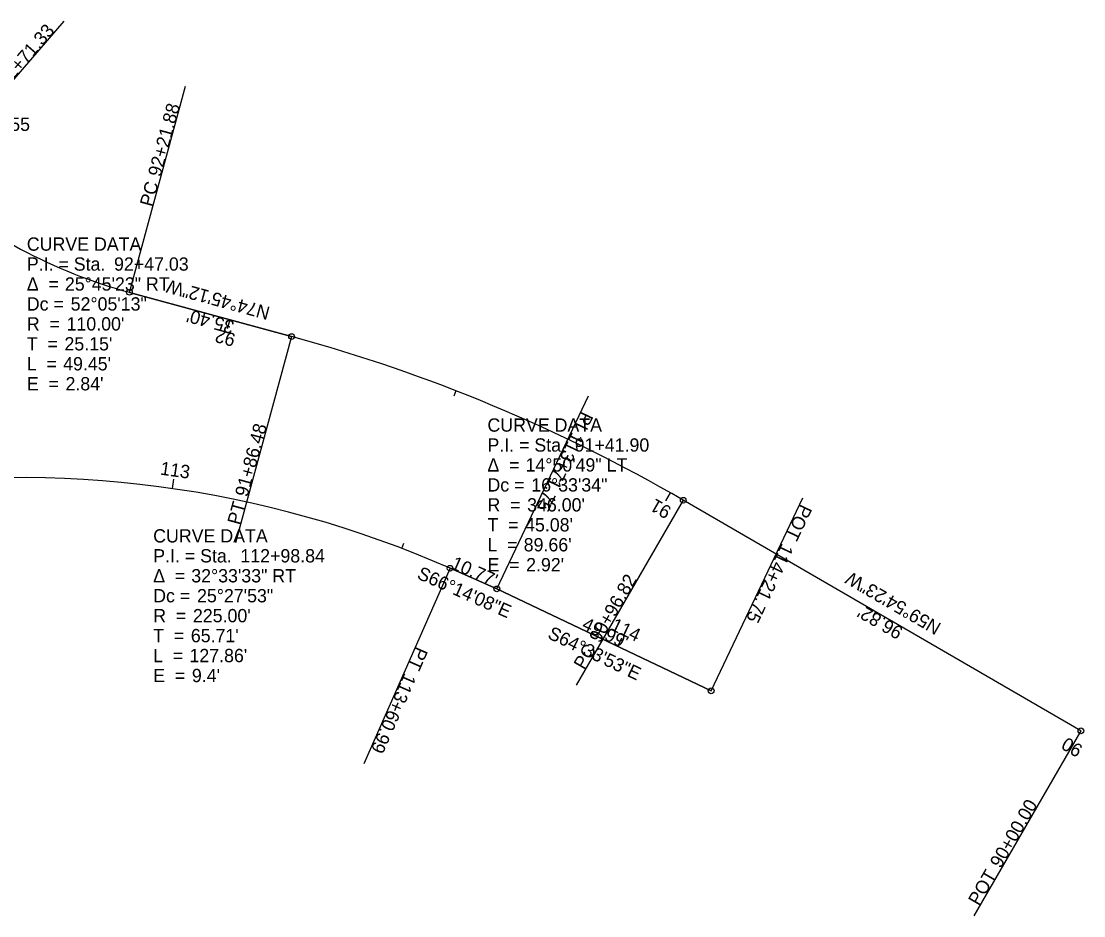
# Model space of a CAD drawing. Extents: x 2047391 to 2047982, y 456752 to 457262.
# Drawn here: x 2047758.1 to 2047982, y 456871 to 457059.3 of the extents above; entities that cross this region are included whole.
import ezdxf

# ---------------------------------------------------------------- set-up
doc = ezdxf.new("R2010")
doc.units = 0
for name, color, linetype in [('GE_P_Alignment', 7, 'Continuous'), ('GE_P_Alignment_100_Bearings', 7, 'Continuous'), ('GE_P_Alignment_100_Cardinal_Points', 7, 'Continuous'), ('GE_P_Alignment_100_Curve_Data', 7, 'Continuous'), ('GE_P_Alignment_100_Distances', 7, 'Continuous'), ('GE_P_Alignment_100_Stations', 7, 'Continuous')]:
    doc.layers.add(name, color=color, linetype=linetype)

msp = doc.modelspace()

# ---------------------------------------------------------------- linework, layer by layer
at = {"layer": 'GE_P_Alignment'}
for p, q in [((2047780.93, 457002.26), (2047815.09, 456992.95)), ((2047815.09, 456992.95), (2047780.93, 457002.26)), ((2047981.35, 456909.94), (2047897.59, 456958.49)), ((2047981.35, 456909.94), (2047897.59, 456958.49)), ((2047981.35, 456909.94), (2047897.59, 456958.49)), ((2047858.32, 456939.83), (2047848.46, 456944.17)), ((2047848.46, 456944.17), (2047858.32, 456939.83)), ((2047903.47, 456918.36), (2047858.32, 456939.83)), ((2047858.32, 456939.83), (2047903.47, 456918.36))]:
    msp.add_line(p, q, dxfattribs=at)
for centre, radius, start, end in [((2047809.86, 457108.39), 110, 228.9967, 254.7532), ((2047809.86, 457108.39), 110, 228.9967, 254.7532), ((2047724.1, 456659.13), 346, 59.9063, 74.7532), ((2047724.1, 456659.13), 346, 59.9063, 74.7532), ((2047757.79, 456738.25), 225, 66.2355, 98.7946), ((2047757.79, 456738.25), 225, 66.2355, 98.7946)]:
    msp.add_arc(centre, radius, start, end, dxfattribs=at)
at = {"layer": 'GE_P_Alignment_100_Cardinal_Points'}
for p, q in [((2047737.69, 457025.37), (2047767.21, 457059.33)), ((2047780.93, 457002.26), (2047792.76, 457045.67)), ((2047815.09, 456992.95), (2047803.25, 456949.53)), ((2047858.32, 456939.83), (2047877.64, 456980.47)), ((2047897.59, 456958.49), (2047875.02, 456919.55)), ((2047903.47, 456918.36), (2047922.79, 456959)), ((2047848.46, 456944.17), (2047830.33, 456902.99)), ((2047981.35, 456909.94), (2047958.79, 456871.01))]:
    msp.add_line(p, q, dxfattribs=at)
for centre in [(2047780.93, 457002.26), (2047815.09, 456992.95), (2047897.59, 456958.49), (2047848.46, 456944.17), (2047858.32, 456939.83), (2047903.47, 456918.36), (2047981.35, 456909.94)]:
    msp.add_circle(centre, 0.6, dxfattribs=at)
at = {"layer": 'GE_P_Alignment_100_Stations'}
for p, q in [((2047802.04, 456996.5), (2047801.51, 456994.57)), ((2047849.71, 456981.52), (2047849.27, 456980.4)), ((2047790.02, 456960.93), (2047790.3, 456962.91)), ((2047894.83, 456960.07), (2047893.84, 456958.33)), ((2047838.3, 456948.35), (2047838.73, 456949.47)), ((2047938.09, 456935.01), (2047937.49, 456933.97)), ((2047883.82, 456927.7), (2047884.68, 456929.51)), ((2047981.35, 456909.94), (2047980.35, 456908.21))]:
    msp.add_line(p, q, dxfattribs=at)

# ---------------------------------------------------------------- texts
at = {"layer": 'GE_P_Alignment_100_Bearings'}
for s, rotation, p in [('N74°45\'12"W', 164.7532, (2047810.72, 456999.11)), ('S66°14\'08"E', 336.2355, (2047841.32, 456942.07)), ('N59°54\'23"W', 149.9063, (2047952.14, 456932.42)), ('S64°33\'53"E', 334.5648, (2047868.83, 456929.52))]:
    msp.add_text(s, height=2.8, rotation=rotation, dxfattribs=at).set_placement(p)
at = {"layer": 'GE_P_Alignment_100_Cardinal_Points'}
for s, rotation, p in [('92+71.33', 48.9967, (2047755.01, 457045.37)), ('92+21.88', 74.7532, (2047787.47, 457026.43)), ('PC', 74.7532, (2047785.75, 457020.13)), ('PI', 244.5648, (2047876.21, 456977.36)), ('91+86.48', 74.7532, (2047805.79, 456959.02)), ('113+71.75', 244.5648, (2047874.16, 456973.04)), ('PT', 74.7532, (2047804.19, 456953.14)), ('POT', 244.5648, (2047922.3, 456957.85)), ('114+21.75', 244.5648, (2047918.38, 456949.6)), ('90+96.82', 59.9063, (2047880.02, 456928.26)), ('PC', 59.9063, (2047876.75, 456922.62)), ('PT', 246.2355, (2047841.33, 456927.85)), ('113+60.99', 246.2355, (2047838.87, 456922.28)), ('90+00.00', 59.9063, (2047964.44, 456880.84)), ('POT', 59.9063, (2047959.86, 456872.94))]:
    msp.add_text(s, height=2.8, rotation=rotation, dxfattribs=at).set_placement(p)
at = {"layer": 'GE_P_Alignment_100_Curve_Data'}
for s, p in [('92+93.55', (2047744.25, 457036.24)), ('CURVE DATA', (2047759.31, 457011.02)), ('P.I. = Sta. ', (2047759.31, 457006.82)), ('92+47.03', (2047777.68, 457006.82)), ('Δ  = ', (2047759.31, 457002.62)), ('25°45\'23" RT', (2047767.33, 457002.62)), ('Dc = ', (2047759.31, 456998.42)), ('52°05\'13"', (2047768.55, 456998.42)), ('R  = ', (2047759.31, 456994.22)), ("110.00'", (2047767.68, 456994.22)), ('T  = ', (2047759.31, 456990.02)), ("25.15'", (2047767.24, 456990.02)), ('L  = ', (2047759.31, 456985.82)), ("49.45'", (2047766.96, 456985.82)), ('E  = ', (2047759.31, 456981.62)), ("2.84'", (2047767.46, 456981.62)), ('CURVE DATA', (2047856.34, 456972.92)), ('P.I. = Sta. ', (2047856.34, 456968.72)), ('91+41.90', (2047874.71, 456968.72)), ('Δ  = ', (2047856.34, 456964.52)), ('14°50\'49" LT', (2047864.36, 456964.52)), ('Dc = ', (2047856.34, 456960.32)), ('16°33\'34"', (2047865.58, 456960.32)), ('R  = ', (2047856.34, 456956.12)), ("346.00'", (2047864.7, 456956.12)), ('T  = ', (2047856.34, 456951.92)), ("45.08'", (2047864.27, 456951.92)), ('CURVE DATA', (2047785.93, 456949.59)), ('L  = ', (2047856.34, 456947.72)), ("89.66'", (2047863.98, 456947.72)), ('P.I. = Sta. ', (2047785.93, 456945.39)), ('112+98.84', (2047804.3, 456945.39)), ('E  = ', (2047856.34, 456943.52)), ("2.92'", (2047864.49, 456943.52)), ('Δ  = ', (2047785.93, 456941.19)), ('32°33\'33" RT', (2047793.95, 456941.19)), ('Dc = ', (2047785.93, 456936.99)), ('25°27\'53"', (2047795.17, 456936.99)), ('R  = ', (2047785.93, 456932.79)), ("225.00'", (2047794.3, 456932.79)), ('T  = ', (2047785.93, 456928.59)), ("65.71'", (2047793.86, 456928.59)), ('L  = ', (2047785.93, 456924.39)), ("127.86'", (2047793.57, 456924.39)), ('E  = ', (2047785.93, 456920.19)), ("9.4'", (2047794.08, 456920.19))]:
    msp.add_text(s, height=2.8, dxfattribs=at).set_placement(p)
at = {"layer": 'GE_P_Alignment_100_Distances'}
for s, rotation, p in [("35.40'", 164.7532, (2047803.2, 456996.14)), ("10.77'", 336.2355, (2047848.47, 456944.22)), ("96.82'", 149.9063, (2047944.12, 456931.47)), ("49.99'", 334.5648, (2047876.04, 456931.46))]:
    msp.add_text(s, height=2.8, rotation=rotation, dxfattribs=at).set_placement(p)
at = {"layer": 'GE_P_Alignment_100_Stations'}
for s, rotation, p in [('92', 164.7532, (2047803.48, 456993.47)), ('113', 351.7663, (2047787.29, 456963.9)), ('91', 150.433, (2047895.33, 456956.86)), ('114', 334.5648, (2047882.1, 456931.29)), ('90', 149.9063, (2047981.98, 456906.64))]:
    msp.add_text(s, height=2.8, rotation=rotation, dxfattribs=at).set_placement(p)

doc.saveas('drawing.dxf')
